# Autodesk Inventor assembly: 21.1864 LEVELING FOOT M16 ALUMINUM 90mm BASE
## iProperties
Created: 2007-03
Part Number: 21.1864 LEVELING FOOT M16 ALUMINUM 90mm BASE
Document SubType Name: Assembly
Designer: Andy Moles
Author: Andy Moles
